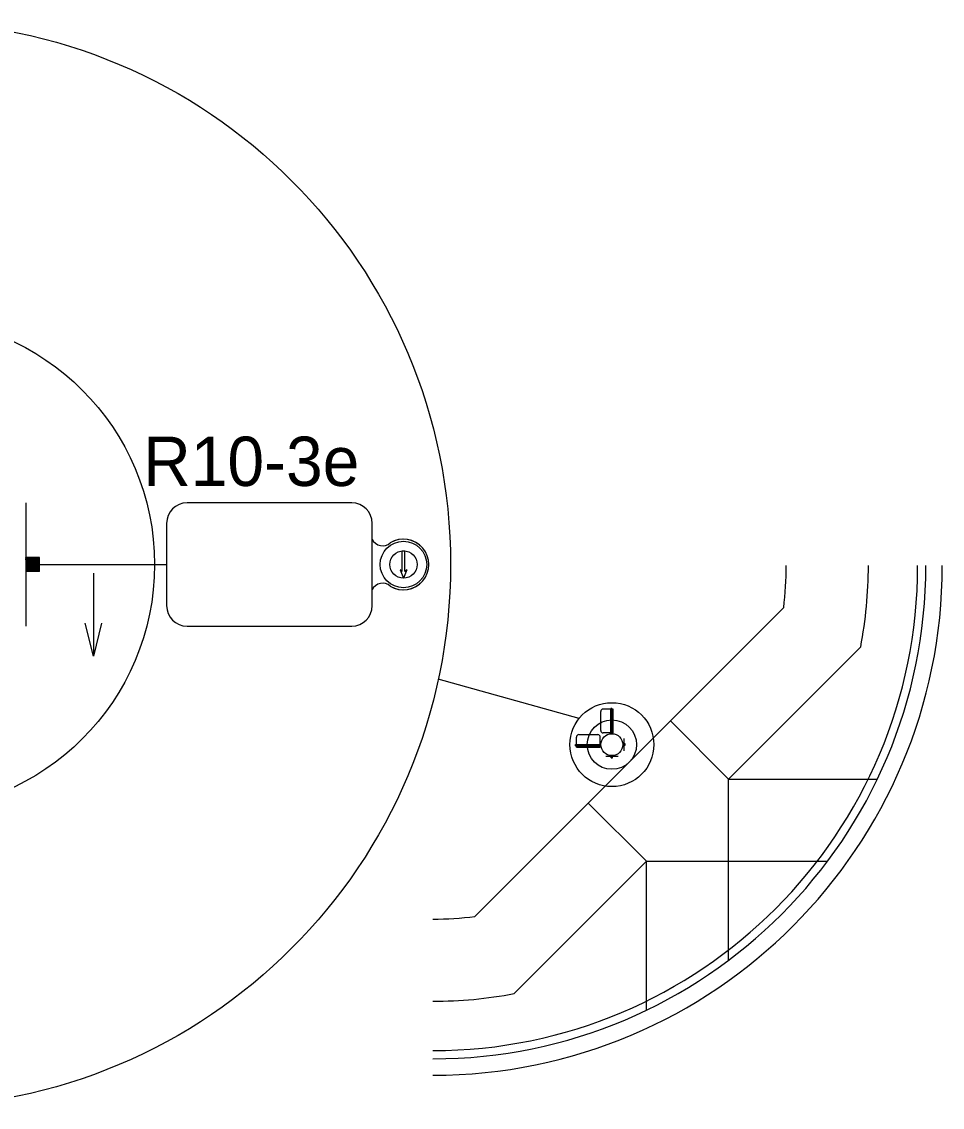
# Model space of a CAD drawing. Extents: x 1369885 to 1370886, y 379976 to 380616.
# Drawn here: x 1370663.8 to 1370747.8, y 380265.3 to 380364.3 of the extents above; entities that cross this region are included whole.
import ezdxf

# ---------------------------------------------------------------- set-up
doc = ezdxf.new("R2010")
doc.units = 0
doc.layers.add('T_Drafting', color=7, linetype='Continuous')

msp = doc.modelspace()

# ---------------------------------------------------------------- linework, layer by layer
at = {"layer": 'T_Drafting'}
for p, q in [((1370664.162, 380320.424), (1370664.162, 380309.174)), ((1370693.915, 380320.424), (1370678.891, 380320.424)), ((1370677.016, 380318.549), (1370677.016, 380311.049)), ((1370695.79, 380311.049), (1370695.79, 380318.549)), ((1370698.527, 380316.04), (1370698.752, 380316.04)), ((1370698.527, 380314.158), (1370698.527, 380316.04)), ((1370698.752, 380314.158), (1370698.752, 380316.04)), ((1370665.412, 380315.424), (1370664.162, 380315.424)), ((1370664.162, 380314.178), (1370665.408, 380315.424)), ((1370664.162, 380314.199), (1370665.387, 380315.424)), ((1370664.162, 380314.22), (1370665.365, 380315.424)), ((1370664.162, 380314.242), (1370665.344, 380315.424)), ((1370664.162, 380314.263), (1370665.323, 380315.424)), ((1370664.162, 380314.284), (1370665.302, 380315.424)), ((1370664.162, 380314.305), (1370665.281, 380315.424)), ((1370664.162, 380314.326), (1370665.259, 380315.424)), ((1370664.162, 380314.348), (1370665.238, 380315.424)), ((1370664.162, 380314.369), (1370665.217, 380315.424)), ((1370664.162, 380314.39), (1370665.196, 380315.424)), ((1370664.162, 380314.411), (1370665.174, 380315.424)), ((1370664.162, 380314.432), (1370665.153, 380315.424)), ((1370664.162, 380314.454), (1370665.132, 380315.424)), ((1370664.162, 380314.475), (1370665.111, 380315.424)), ((1370664.162, 380314.496), (1370665.09, 380315.424)), ((1370664.162, 380314.517), (1370665.068, 380315.424)), ((1370664.162, 380314.539), (1370665.047, 380315.424)), ((1370664.162, 380314.56), (1370665.026, 380315.424)), ((1370664.162, 380314.581), (1370665.005, 380315.424)), ((1370664.162, 380314.602), (1370664.984, 380315.424)), ((1370664.162, 380314.623), (1370664.962, 380315.424)), ((1370664.162, 380314.645), (1370664.941, 380315.424)), ((1370664.162, 380314.666), (1370664.92, 380315.424)), ((1370664.162, 380314.687), (1370664.899, 380315.424)), ((1370664.162, 380314.708), (1370664.877, 380315.424)), ((1370664.162, 380314.729), (1370664.856, 380315.424)), ((1370664.162, 380314.751), (1370664.835, 380315.424)), ((1370664.162, 380314.772), (1370664.814, 380315.424)), ((1370664.162, 380314.793), (1370664.793, 380315.424)), ((1370664.162, 380314.814), (1370664.771, 380315.424)), ((1370664.162, 380314.836), (1370664.75, 380315.424)), ((1370664.162, 380314.857), (1370664.729, 380315.424)), ((1370664.162, 380314.878), (1370664.708, 380315.424)), ((1370664.162, 380314.899), (1370664.687, 380315.424)), ((1370664.162, 380314.92), (1370664.665, 380315.424)), ((1370664.162, 380314.942), (1370664.644, 380315.424)), ((1370664.162, 380314.963), (1370664.623, 380315.424)), ((1370664.162, 380314.984), (1370664.602, 380315.424)), ((1370664.162, 380315.005), (1370664.581, 380315.424)), ((1370664.162, 380315.026), (1370664.559, 380315.424)), ((1370664.162, 380315.048), (1370664.538, 380315.424)), ((1370664.162, 380315.069), (1370664.517, 380315.424)), ((1370664.162, 380315.09), (1370664.496, 380315.424)), ((1370664.162, 380315.111), (1370664.474, 380315.424)), ((1370664.162, 380315.133), (1370664.453, 380315.424)), ((1370664.162, 380315.154), (1370664.432, 380315.424)), ((1370664.162, 380315.175), (1370664.411, 380315.424)), ((1370664.162, 380315.196), (1370664.39, 380315.424)), ((1370664.162, 380315.217), (1370664.368, 380315.424)), ((1370664.162, 380315.239), (1370664.347, 380315.424)), ((1370664.162, 380315.26), (1370664.326, 380315.424)), ((1370664.162, 380315.281), (1370664.305, 380315.424)), ((1370664.162, 380315.302), (1370664.284, 380315.424)), ((1370664.162, 380315.323), (1370664.262, 380315.424)), ((1370664.162, 380315.345), (1370664.241, 380315.424)), ((1370664.162, 380315.366), (1370664.22, 380315.424)), ((1370664.162, 380315.387), (1370664.199, 380315.424)), ((1370664.162, 380315.408), (1370664.177, 380315.424)), ((1370664.179, 380314.174), (1370665.412, 380315.407)), ((1370664.2, 380314.174), (1370665.412, 380315.386)), ((1370664.221, 380314.174), (1370665.412, 380315.364)), ((1370664.243, 380314.174), (1370665.412, 380315.343)), ((1370664.264, 380314.174), (1370665.412, 380315.322)), ((1370664.285, 380314.174), (1370665.412, 380315.301)), ((1370664.306, 380314.174), (1370665.412, 380315.279)), ((1370664.328, 380314.174), (1370665.412, 380315.258)), ((1370664.349, 380314.174), (1370665.412, 380315.237)), ((1370664.37, 380314.174), (1370665.412, 380315.216)), ((1370664.391, 380314.174), (1370665.412, 380315.195)), ((1370664.412, 380314.174), (1370665.412, 380315.173)), ((1370664.434, 380314.174), (1370665.412, 380315.152)), ((1370664.455, 380314.174), (1370665.412, 380315.131)), ((1370664.476, 380314.174), (1370665.412, 380315.11)), ((1370664.497, 380314.174), (1370665.412, 380315.089)), ((1370664.518, 380314.174), (1370665.412, 380315.067)), ((1370664.54, 380314.174), (1370665.412, 380315.046)), ((1370664.561, 380314.174), (1370665.412, 380315.025)), ((1370664.582, 380314.174), (1370665.412, 380315.004)), ((1370664.603, 380314.174), (1370665.412, 380314.982)), ((1370664.625, 380314.174), (1370665.412, 380314.961)), ((1370664.646, 380314.174), (1370665.412, 380314.94)), ((1370664.667, 380314.174), (1370665.412, 380314.919)), ((1370664.688, 380314.174), (1370665.412, 380314.898)), ((1370664.709, 380314.174), (1370665.412, 380314.876)), ((1370664.731, 380314.174), (1370665.412, 380314.855)), ((1370664.752, 380314.174), (1370665.412, 380314.834)), ((1370664.773, 380314.174), (1370665.412, 380314.813)), ((1370664.794, 380314.174), (1370665.412, 380314.792)), ((1370664.815, 380314.174), (1370665.412, 380314.77)), ((1370664.837, 380314.174), (1370665.412, 380314.749)), ((1370664.858, 380314.174), (1370665.412, 380314.728)), ((1370664.879, 380314.174), (1370665.412, 380314.707)), ((1370664.9, 380314.174), (1370665.412, 380314.685)), ((1370664.921, 380314.174), (1370665.412, 380314.664)), ((1370664.943, 380314.174), (1370665.412, 380314.643)), ((1370664.964, 380314.174), (1370665.412, 380314.622)), ((1370664.985, 380314.174), (1370665.412, 380314.601)), ((1370665.006, 380314.174), (1370665.412, 380314.579)), ((1370665.028, 380314.174), (1370665.412, 380314.558)), ((1370665.049, 380314.174), (1370665.412, 380314.537)), ((1370665.412, 380314.174), (1370665.412, 380315.424)), ((1370665.412, 380314.799), (1370677.016, 380314.799)), ((1370665.412, 380314.174), (1370664.162, 380314.174)), ((1370665.07, 380314.174), (1370665.412, 380314.516)), ((1370665.091, 380314.174), (1370665.412, 380314.495)), ((1370665.112, 380314.174), (1370665.412, 380314.473)), ((1370665.134, 380314.174), (1370665.412, 380314.452)), ((1370665.155, 380314.174), (1370665.412, 380314.431)), ((1370665.176, 380314.174), (1370665.412, 380314.41)), ((1370665.197, 380314.174), (1370665.412, 380314.388)), ((1370665.218, 380314.174), (1370665.412, 380314.367)), ((1370665.24, 380314.174), (1370665.412, 380314.346)), ((1370665.261, 380314.174), (1370665.412, 380314.325)), ((1370665.282, 380314.174), (1370665.412, 380314.304)), ((1370665.303, 380314.174), (1370665.412, 380314.282)), ((1370665.325, 380314.174), (1370665.412, 380314.261)), ((1370665.346, 380314.174), (1370665.412, 380314.24)), ((1370665.367, 380314.174), (1370665.412, 380314.219)), ((1370665.388, 380314.174), (1370665.412, 380314.198)), ((1370665.409, 380314.174), (1370665.412, 380314.176)), ((1370670.328, 380313.999), (1370670.328, 380306.45)), ((1370698.34, 380314.308), (1370698.64, 380313.549)), ((1370698.527, 380314.158), (1370698.34, 380314.308)), ((1370698.94, 380314.308), (1370698.64, 380313.549)), ((1370698.94, 380314.308), (1370698.752, 380314.158)), ((1370705.167, 380282.677), (1370733.355, 380310.866)), ((1370678.891, 380309.174), (1370693.915, 380309.174)), ((1370728.315, 380295.218), (1370740.388, 380307.291)), ((1370714.676, 380300.749), (1370701.822, 380304.351)), ((1370717.558, 380299.362), (1370717.558, 380301.675)), ((1370717.67, 380301.675), (1370717.558, 380301.675)), ((1370717.67, 380299.362), (1370717.67, 380301.675)), ((1370716.645, 380299.656), (1370716.645, 380301.381)), ((1370717.558, 380301.606), (1370716.87, 380301.606)), ((1370717.783, 380301.606), (1370717.67, 380301.606)), ((1370717.783, 380299.431), (1370717.783, 380301.606)), ((1370723.011, 380300.521), (1370728.315, 380295.218)), ((1370714.427, 380298.362), (1370714.427, 380299.05)), ((1370714.652, 380299.275), (1370716.377, 380299.275)), ((1370716.602, 380298.362), (1370716.602, 380299.05)), ((1370717.558, 380299.431), (1370716.87, 380299.431)), ((1370717.67, 380299.362), (1370717.558, 380299.362)), ((1370717.783, 380299.431), (1370717.67, 380299.431)), ((1370718.745, 380298.925), (1370718.745, 380297.8)), ((1370714.358, 380298.362), (1370716.67, 380298.362)), ((1370714.358, 380298.25), (1370714.358, 380298.362)), ((1370714.358, 380298.25), (1370716.67, 380298.25)), ((1370714.427, 380298.137), (1370714.427, 380298.25)), ((1370714.427, 380298.137), (1370716.602, 380298.137)), ((1370716.602, 380298.137), (1370716.602, 380298.25)), ((1370716.67, 380298.25), (1370716.67, 380298.362)), ((1370718.87, 380298.425), (1370718.745, 380298.425)), ((1370718.745, 380298.3), (1370718.87, 380298.425)), ((1370718.745, 380298.303), (1370718.868, 380298.425)), ((1370718.745, 380298.305), (1370718.866, 380298.425)), ((1370718.745, 380298.307), (1370718.863, 380298.425)), ((1370718.745, 380298.309), (1370718.861, 380298.425)), ((1370718.745, 380298.311), (1370718.859, 380298.425)), ((1370718.745, 380298.313), (1370718.857, 380298.425)), ((1370718.745, 380298.315), (1370718.855, 380298.425)), ((1370718.745, 380298.317), (1370718.853, 380298.425)), ((1370718.745, 380298.32), (1370718.851, 380298.425)), ((1370718.745, 380298.322), (1370718.849, 380298.425)), ((1370718.745, 380298.324), (1370718.847, 380298.425)), ((1370718.745, 380298.326), (1370718.844, 380298.425)), ((1370718.745, 380298.328), (1370718.842, 380298.425)), ((1370718.745, 380298.33), (1370718.84, 380298.425)), ((1370718.745, 380298.332), (1370718.838, 380298.425)), ((1370718.745, 380298.334), (1370718.836, 380298.425)), ((1370718.745, 380298.336), (1370718.834, 380298.425)), ((1370718.745, 380298.339), (1370718.832, 380298.425)), ((1370718.745, 380298.341), (1370718.83, 380298.425)), ((1370718.745, 380298.343), (1370718.827, 380298.425)), ((1370718.745, 380298.345), (1370718.825, 380298.425)), ((1370718.745, 380298.347), (1370718.823, 380298.425)), ((1370718.745, 380298.349), (1370718.821, 380298.425)), ((1370718.745, 380298.351), (1370718.819, 380298.425)), ((1370718.745, 380298.353), (1370718.817, 380298.425)), ((1370718.745, 380298.356), (1370718.815, 380298.425)), ((1370718.745, 380298.358), (1370718.813, 380298.425)), ((1370718.745, 380298.36), (1370718.81, 380298.425)), ((1370718.745, 380298.362), (1370718.808, 380298.425)), ((1370718.745, 380298.364), (1370718.806, 380298.425)), ((1370718.745, 380298.366), (1370718.804, 380298.425)), ((1370718.745, 380298.368), (1370718.802, 380298.425)), ((1370718.745, 380298.37), (1370718.8, 380298.425)), ((1370718.745, 380298.373), (1370718.798, 380298.425)), ((1370718.745, 380298.375), (1370718.796, 380298.425)), ((1370718.745, 380298.377), (1370718.793, 380298.425)), ((1370718.745, 380298.379), (1370718.791, 380298.425)), ((1370718.745, 380298.381), (1370718.789, 380298.425)), ((1370718.745, 380298.383), (1370718.787, 380298.425)), ((1370718.745, 380298.385), (1370718.785, 380298.425)), ((1370718.745, 380298.387), (1370718.783, 380298.425)), ((1370718.745, 380298.39), (1370718.781, 380298.425)), ((1370718.745, 380298.392), (1370718.779, 380298.425)), ((1370718.745, 380298.394), (1370718.777, 380298.425)), ((1370718.745, 380298.396), (1370718.774, 380298.425)), ((1370718.745, 380298.398), (1370718.772, 380298.425)), ((1370718.745, 380298.4), (1370718.77, 380298.425)), ((1370718.745, 380298.402), (1370718.768, 380298.425)), ((1370718.745, 380298.404), (1370718.766, 380298.425)), ((1370718.745, 380298.406), (1370718.764, 380298.425)), ((1370718.745, 380298.409), (1370718.762, 380298.425)), ((1370718.745, 380298.411), (1370718.76, 380298.425)), ((1370718.745, 380298.413), (1370718.757, 380298.425)), ((1370718.745, 380298.415), (1370718.755, 380298.425)), ((1370718.745, 380298.417), (1370718.753, 380298.425)), ((1370718.745, 380298.419), (1370718.751, 380298.425)), ((1370718.745, 380298.421), (1370718.749, 380298.425)), ((1370718.745, 380298.423), (1370718.747, 380298.425)), ((1370718.87, 380298.3), (1370718.745, 380298.3)), ((1370718.747, 380298.3), (1370718.87, 380298.423)), ((1370718.749, 380298.3), (1370718.87, 380298.421)), ((1370718.751, 380298.3), (1370718.87, 380298.419)), ((1370718.753, 380298.3), (1370718.87, 380298.417)), ((1370718.755, 380298.3), (1370718.87, 380298.415)), ((1370718.758, 380298.3), (1370718.87, 380298.413)), ((1370718.76, 380298.3), (1370718.87, 380298.411)), ((1370718.762, 380298.3), (1370718.87, 380298.408)), ((1370718.764, 380298.3), (1370718.87, 380298.406)), ((1370718.766, 380298.3), (1370718.87, 380298.404)), ((1370718.768, 380298.3), (1370718.87, 380298.402)), ((1370718.77, 380298.3), (1370718.87, 380298.4)), ((1370718.772, 380298.3), (1370718.87, 380298.398)), ((1370718.775, 380298.3), (1370718.87, 380298.396)), ((1370718.777, 380298.3), (1370718.87, 380298.394)), ((1370718.779, 380298.3), (1370718.87, 380298.391)), ((1370718.781, 380298.3), (1370718.87, 380298.389)), ((1370718.783, 380298.3), (1370718.87, 380298.387)), ((1370718.785, 380298.3), (1370718.87, 380298.385)), ((1370718.787, 380298.3), (1370718.87, 380298.383)), ((1370718.789, 380298.3), (1370718.87, 380298.381)), ((1370718.792, 380298.3), (1370718.87, 380298.379)), ((1370718.794, 380298.3), (1370718.87, 380298.377)), ((1370718.796, 380298.3), (1370718.87, 380298.375)), ((1370718.798, 380298.3), (1370718.87, 380298.372)), ((1370718.8, 380298.3), (1370718.87, 380298.37)), ((1370718.802, 380298.3), (1370718.87, 380298.368)), ((1370718.804, 380298.3), (1370718.87, 380298.366)), ((1370718.806, 380298.3), (1370718.87, 380298.364)), ((1370718.808, 380298.3), (1370718.87, 380298.362)), ((1370718.811, 380298.3), (1370718.87, 380298.36)), ((1370718.813, 380298.3), (1370718.87, 380298.358)), ((1370718.815, 380298.3), (1370718.87, 380298.355)), ((1370718.817, 380298.3), (1370718.87, 380298.353)), ((1370718.819, 380298.3), (1370718.87, 380298.351)), ((1370718.821, 380298.3), (1370718.87, 380298.349)), ((1370718.823, 380298.3), (1370718.87, 380298.347)), ((1370718.825, 380298.3), (1370718.87, 380298.345)), ((1370718.828, 380298.3), (1370718.87, 380298.343)), ((1370718.83, 380298.3), (1370718.87, 380298.341)), ((1370718.832, 380298.3), (1370718.87, 380298.338)), ((1370718.834, 380298.3), (1370718.87, 380298.336)), ((1370718.836, 380298.3), (1370718.87, 380298.334)), ((1370718.838, 380298.3), (1370718.87, 380298.332)), ((1370718.84, 380298.3), (1370718.87, 380298.33)), ((1370718.842, 380298.3), (1370718.87, 380298.328)), ((1370718.845, 380298.3), (1370718.87, 380298.326)), ((1370718.847, 380298.3), (1370718.87, 380298.324)), ((1370718.849, 380298.3), (1370718.87, 380298.321)), ((1370718.851, 380298.3), (1370718.87, 380298.319)), ((1370718.853, 380298.3), (1370718.87, 380298.317)), ((1370718.855, 380298.3), (1370718.87, 380298.315)), ((1370718.857, 380298.3), (1370718.87, 380298.313)), ((1370718.859, 380298.3), (1370718.87, 380298.311)), ((1370718.862, 380298.3), (1370718.87, 380298.309)), ((1370718.864, 380298.3), (1370718.87, 380298.307)), ((1370718.866, 380298.3), (1370718.87, 380298.305)), ((1370718.868, 380298.3), (1370718.87, 380298.302)), ((1370718.87, 380298.3), (1370718.87, 380298.425)), ((1370718.87, 380298.3), (1370718.87, 380298.3)), ((1370718.233, 380297.287), (1370717.108, 380297.287)), ((1370717.608, 380297.162), (1370717.608, 380297.287)), ((1370717.608, 380297.163), (1370717.732, 380297.287)), ((1370717.608, 380297.166), (1370717.73, 380297.287)), ((1370717.608, 380297.168), (1370717.728, 380297.287)), ((1370717.608, 380297.17), (1370717.726, 380297.287)), ((1370717.608, 380297.172), (1370717.723, 380297.287)), ((1370717.608, 380297.174), (1370717.721, 380297.287)), ((1370717.608, 380297.176), (1370717.719, 380297.287)), ((1370717.608, 380297.178), (1370717.717, 380297.287)), ((1370717.608, 380297.18), (1370717.715, 380297.287)), ((1370717.608, 380297.182), (1370717.713, 380297.287)), ((1370717.608, 380297.185), (1370717.711, 380297.287)), ((1370717.608, 380297.187), (1370717.709, 380297.287)), ((1370717.608, 380297.189), (1370717.706, 380297.287)), ((1370717.608, 380297.191), (1370717.704, 380297.287)), ((1370717.608, 380297.193), (1370717.702, 380297.287)), ((1370717.608, 380297.195), (1370717.7, 380297.287)), ((1370717.608, 380297.197), (1370717.698, 380297.287)), ((1370717.608, 380297.199), (1370717.696, 380297.287)), ((1370717.608, 380297.202), (1370717.694, 380297.287)), ((1370717.608, 380297.204), (1370717.692, 380297.287)), ((1370717.608, 380297.206), (1370717.689, 380297.287)), ((1370717.608, 380297.208), (1370717.687, 380297.287)), ((1370717.608, 380297.21), (1370717.685, 380297.287)), ((1370717.608, 380297.212), (1370717.683, 380297.287)), ((1370717.608, 380297.214), (1370717.681, 380297.287)), ((1370717.608, 380297.216), (1370717.679, 380297.287)), ((1370717.608, 380297.219), (1370717.677, 380297.287)), ((1370717.608, 380297.221), (1370717.675, 380297.287)), ((1370717.608, 380297.223), (1370717.672, 380297.287)), ((1370717.608, 380297.225), (1370717.67, 380297.287)), ((1370717.608, 380297.227), (1370717.668, 380297.287)), ((1370717.608, 380297.229), (1370717.666, 380297.287)), ((1370717.608, 380297.231), (1370717.664, 380297.287)), ((1370717.608, 380297.233), (1370717.662, 380297.287)), ((1370717.608, 380297.236), (1370717.66, 380297.287)), ((1370717.608, 380297.238), (1370717.658, 380297.287)), ((1370717.608, 380297.24), (1370717.656, 380297.287)), ((1370717.608, 380297.242), (1370717.653, 380297.287)), ((1370717.608, 380297.244), (1370717.651, 380297.287)), ((1370717.608, 380297.246), (1370717.649, 380297.287)), ((1370717.608, 380297.248), (1370717.647, 380297.287)), ((1370717.608, 380297.25), (1370717.645, 380297.287)), ((1370717.608, 380297.252), (1370717.643, 380297.287)), ((1370717.608, 380297.255), (1370717.641, 380297.287)), ((1370717.608, 380297.257), (1370717.639, 380297.287)), ((1370717.608, 380297.259), (1370717.636, 380297.287)), ((1370717.608, 380297.261), (1370717.634, 380297.287)), ((1370717.608, 380297.263), (1370717.632, 380297.287)), ((1370717.608, 380297.265), (1370717.63, 380297.287)), ((1370717.608, 380297.267), (1370717.628, 380297.287)), ((1370717.608, 380297.269), (1370717.626, 380297.287)), ((1370717.608, 380297.272), (1370717.624, 380297.287)), ((1370717.608, 380297.274), (1370717.622, 380297.287)), ((1370717.608, 380297.276), (1370717.619, 380297.287)), ((1370717.608, 380297.278), (1370717.617, 380297.287)), ((1370717.608, 380297.28), (1370717.615, 380297.287)), ((1370717.608, 380297.282), (1370717.613, 380297.287)), ((1370717.608, 380297.284), (1370717.611, 380297.287)), ((1370717.608, 380297.286), (1370717.609, 380297.287)), ((1370717.608, 380297.162), (1370717.733, 380297.162)), ((1370717.609, 380297.162), (1370717.733, 380297.286)), ((1370717.611, 380297.162), (1370717.733, 380297.284)), ((1370717.613, 380297.162), (1370717.733, 380297.282)), ((1370717.615, 380297.162), (1370717.733, 380297.28)), ((1370717.617, 380297.162), (1370717.733, 380297.278)), ((1370717.62, 380297.162), (1370717.733, 380297.276)), ((1370717.622, 380297.162), (1370717.733, 380297.274)), ((1370717.624, 380297.162), (1370717.733, 380297.271)), ((1370717.626, 380297.162), (1370717.733, 380297.269)), ((1370717.628, 380297.162), (1370717.733, 380297.267)), ((1370717.63, 380297.162), (1370717.733, 380297.265)), ((1370717.632, 380297.162), (1370717.733, 380297.263)), ((1370717.634, 380297.162), (1370717.733, 380297.261)), ((1370717.637, 380297.162), (1370717.733, 380297.259)), ((1370717.639, 380297.162), (1370717.733, 380297.257)), ((1370717.641, 380297.162), (1370717.733, 380297.254)), ((1370717.643, 380297.162), (1370717.733, 380297.252)), ((1370717.645, 380297.162), (1370717.733, 380297.25)), ((1370717.647, 380297.162), (1370717.733, 380297.248)), ((1370717.649, 380297.162), (1370717.733, 380297.246)), ((1370717.651, 380297.162), (1370717.733, 380297.244)), ((1370717.654, 380297.162), (1370717.733, 380297.242)), ((1370717.656, 380297.162), (1370717.733, 380297.24)), ((1370717.658, 380297.162), (1370717.733, 380297.237)), ((1370717.66, 380297.162), (1370717.733, 380297.235)), ((1370717.662, 380297.162), (1370717.733, 380297.233)), ((1370717.664, 380297.162), (1370717.733, 380297.231)), ((1370717.666, 380297.162), (1370717.733, 380297.229)), ((1370717.668, 380297.162), (1370717.733, 380297.227)), ((1370717.671, 380297.162), (1370717.733, 380297.225)), ((1370717.673, 380297.162), (1370717.733, 380297.223)), ((1370717.675, 380297.162), (1370717.733, 380297.221)), ((1370717.677, 380297.162), (1370717.733, 380297.218)), ((1370717.679, 380297.162), (1370717.733, 380297.216)), ((1370717.681, 380297.162), (1370717.733, 380297.214)), ((1370717.683, 380297.162), (1370717.733, 380297.212)), ((1370717.685, 380297.162), (1370717.733, 380297.21)), ((1370717.687, 380297.162), (1370717.733, 380297.208)), ((1370717.69, 380297.162), (1370717.733, 380297.206)), ((1370717.692, 380297.162), (1370717.733, 380297.204)), ((1370717.694, 380297.162), (1370717.733, 380297.201)), ((1370717.696, 380297.162), (1370717.733, 380297.199)), ((1370717.698, 380297.162), (1370717.733, 380297.197)), ((1370717.7, 380297.162), (1370717.733, 380297.195)), ((1370717.702, 380297.162), (1370717.733, 380297.193)), ((1370717.704, 380297.162), (1370717.733, 380297.191)), ((1370717.707, 380297.162), (1370717.733, 380297.189)), ((1370717.709, 380297.162), (1370717.733, 380297.187)), ((1370717.711, 380297.162), (1370717.733, 380297.184)), ((1370717.713, 380297.162), (1370717.733, 380297.182)), ((1370717.715, 380297.162), (1370717.733, 380297.18)), ((1370717.717, 380297.162), (1370717.733, 380297.178)), ((1370717.719, 380297.162), (1370717.733, 380297.176)), ((1370717.721, 380297.162), (1370717.733, 380297.174)), ((1370717.724, 380297.162), (1370717.733, 380297.172)), ((1370717.726, 380297.162), (1370717.733, 380297.17)), ((1370717.728, 380297.162), (1370717.733, 380297.167)), ((1370717.73, 380297.162), (1370717.733, 380297.165)), ((1370717.732, 380297.162), (1370717.733, 380297.163)), ((1370717.733, 380297.162), (1370717.733, 380297.287)), ((1370728.315, 380278.684), (1370728.315, 380295.218)), ((1370728.315, 380295.218), (1370741.899, 380295.218)), ((1370715.511, 380293.021), (1370720.815, 380287.718)), ((1370708.741, 380275.645), (1370720.815, 380287.718)), ((1370720.815, 380287.718), (1370737.349, 380287.718)), ((1370720.815, 380274.134), (1370720.815, 380287.718))]:
    msp.add_line(p, q, dxfattribs=at)
msp.add_lwpolyline([(1370671.078, 380309.45), (1370670.328, 380306.45), (1370669.578, 380309.45)], dxfattribs=at)
for centre, radius in [((1370653.412, 380314.799), 49.525), ((1370653.412, 380314.799), 22.5), ((1370698.64, 380314.799), 2.125), ((1370698.64, 380314.799), 1.25), ((1370717.67, 380298.362), 3.829), ((1370717.67, 380298.362), 2.25), ((1370717.67, 380298.362), 1)]:
    msp.add_circle(centre, radius, dxfattribs=at)
for centre, radius, start, end in [((1370678.891, 380318.549), 1.875, 90, 180), ((1370693.915, 380318.549), 1.875, 0, 90), ((1370696.74, 380317.558), 1.05, 205.19558, 311.80279), ((1370698.64, 380314.799), 2.313, 238.74024, 121.25976), ((1370698.64, 380314.799), 2.313, 42.50664, 121.25976), ((1370701.334, 380314.699), 45, 270, 0), ((1370701.334, 380314.699), 46.5, 270, 0), ((1370701.334, 380314.699), 44.25, 270, 0), ((1370701.334, 380314.699), 32.25, 353.17407, 360), ((1370701.334, 380314.699), 39.75, 349.26033, 0), ((1370696.74, 380312.039), 1.05, 48.19721, 154.80442), ((1370698.64, 380314.799), 2.313, 238.74024, 317.49336), ((1370678.891, 380311.049), 1.875, 180, 270), ((1370693.915, 380311.049), 1.875, 270, 0), ((1370716.87, 380301.381), 0.225, 90, 180), ((1370714.652, 380299.05), 0.225, 90, 180), ((1370716.377, 380299.05), 0.225, 360, 90), ((1370716.87, 380299.656), 0.225, 180, 270), ((1370701.334, 380314.699), 32.25, 270, 276.82593), ((1370701.334, 380314.699), 39.75, 270, 280.73967)]:
    msp.add_arc(centre, radius, start, end, dxfattribs=at)

# ---------------------------------------------------------------- texts
msp.add_text('R10-3e', height=4.5, dxfattribs=at).set_placement((1370674.879, 380321.963))

doc.saveas('drawing.dxf')
